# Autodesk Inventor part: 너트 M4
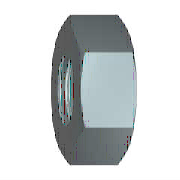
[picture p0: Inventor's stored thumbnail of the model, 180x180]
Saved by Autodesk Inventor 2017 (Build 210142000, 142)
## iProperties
Created: 2012-02
Part Number: 너트 M4
Material: 강철, 연강
Description: 6각 너트 및 6각 가는 너트 - 스타일 1
Document SubType Name: Modeling
Standard: KS B 1012
Designer: mduedu
Standards Organization: KS
Language: ko-KR
Size Designation: A M4
Categories: <MemberInstance><Categories><Category DisplayName="조임쇠" InternalName="e4da775c-781d-43d5-af7c-5136215cf5a6" Mnemonic="FSTN"><Category DisplayName="너트" InternalN
Density: 7.86 g/cm^3
Mass: 0.846697 g
Surface Area: 1.71448 cm^2
Volume: 0.107722 cm^3
Appearance: 강철
IsCustomPart: 0
Author: mduedu
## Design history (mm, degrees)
sketch "스케치1"
  geometry: L1 (-4.041, 0)-(-2.021, 3.5); L2 (-2.021, 3.5)-(2.021, 3.5); L3 (2.021, 3.5)-(4.041, 0); L4 (4.041, 0)-(2.021, -3.5); L5 (2.021, -3.5)-(-2.021, -3.5); L6 (-2.021, -3.5)-(-4.041, 0); 2 further points
  constraints: 12 end point, 1 coincident, 1 horizontal, 11 other
  dimensions: "d0" = 8.0829 distance of L3.end L1.start (= 1.1547 x SW)
extrude "본체" new body sketch "스케치1" distance "d1" = 3.2 (= KOH); taper "d2" = 0 deg
sketch "스케치2"
  geometry: L1 (0, 2.021)-(0, 4.041) reference; L2 (0, 4.041)-(3.2, 4.041) reference; L3 (3.2, 2.021)-(3.2, 4.041) reference; L4 (-0.64, 0)-(3.84, 0) reference; L5 (0.313, 4.041)-(0, 3.5); L6 (2.887, 4.041)-(3.2, 3.5)
  constraints: 4 end point, 4 point on line
  dimensions: "d3" = 30 deg angle of L1 L5 (= ANG1); "d4" = 30 deg angle of L3 L6 (= ANG2); "d5" = 7 diameter of L5.end L4 (= SW0); "d6" = 7 diameter of L6.end L4 (= SW01)
revolve "모따기1" sketch "스케치2" stored, may be unused: angle "d7" = 90 deg
sketch "스케치3"
  geometry: A1 r 3.5 centre (0, 0) between (-1.75, -3.031) and (1.75, -3.031) reference; 1 further point
  constraints: 1 coincident
hole "스레드" sketch "스케치3" at (0, 0) diameter "d25" = 3.242; stored, may be unused: countersink angle "d29" = 82 deg, drill point angle "d31" = 118 deg; dims "d26" = 6, "d27" = 4, "d28" = 2, "d30" = 8
workaxis "Work Axis1"
workplane "Work Plane1"
body "Solid1"
chamfer "모따기2" distance "d8" = 0.37889 (= -0.5 x GD1 + 0.5 x NND); stored, may be unused: angle "d9" = 30 deg, second distance "d40" = 0.37889 (= -0.5 x GD1 + 0.5 x NND)
chamfer "모따기3" distance "d10" = 0.37889 (= -0.5 x GD1 + 0.5 x NND); stored, may be unused: angle "d11" = 30 deg, second distance "d41" = 0.37889 (= -0.5 x GD1 + 0.5 x NND)
other parameters: "ANG1" = 30 deg [user parameter; used in 1 equation term], "ANG2" = 30 deg [user parameter; used in 1 equation term], "NND" = 4 [user parameter; used in 4 equation terms], "KOH" = 3.2 [user parameter; used in 1 equation term], "SW" = 7 [user parameter; used in 4 equation terms], "SW0" = 7 (= SW) [user parameter; used in 1 equation term], "SW01" = 7 (= SW) [user parameter; used in 1 equation term], "GD1" = 3.24223 (computed from THREADDIA, PTC, TOA) [user parameter; used in 4 equation terms], "d13" = 0, "d14" = 0, "d39" = 0, "d42" = 0, "GUL" = 0.37889 (= 0.541266 x PTC) [user parameter], "TPU" = 14.28571 (computed from PTC) [user parameter], "THREADDIA" = 4 [user parameter; used in 1 equation term], "TOA" = 30 deg [user parameter; used in 1 equation term], "PTC" = 0.7 [user parameter; used in 4 equation terms], "E0" = 8.085 (= 1.155 x SW) [user parameter], "GAL" = 0.37889 (= 0.541266 x PTC) [user parameter]
